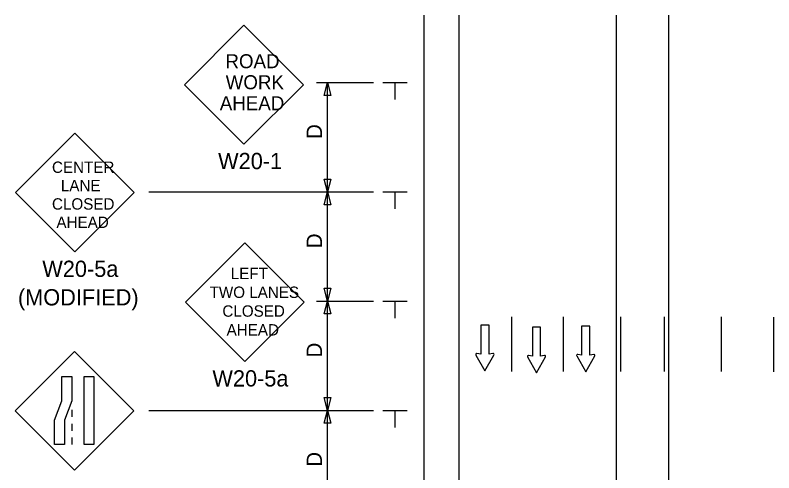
# Model space of a CAD drawing. Extents: x 16646 to 19498, y 2812 to 4437.
# Drawn here: x 16735.5 to 17082.8, y 3789.1 to 3998.5 of the extents above; entities that cross this region are included whole.
import ezdxf

# ---------------------------------------------------------------- set-up
doc = ezdxf.new("R2010")
doc.units = 0
for name, color, linetype in [('ALI_LEGAL_EX', 7, 'Continuous'), ('MT_SCRATCH_LEVEL_E', 7, 'Continuous'), ('PAVT_EDGE_EX', 7, 'Continuous'), ('TRAFFIC_SIGNS_PR', 7, 'Continuous'), ('TYPICAL_EX', 7, 'Continuous'), ('TYPICAL_TEXT_DIMEN_PR', 7, 'Continuous')]:
    doc.layers.add(name, color=color, linetype=linetype)

msp = doc.modelspace()

# ---------------------------------------------------------------- linework, layer by layer
at = {"layer": 'ALI_LEGAL_EX'}
for points in [[(16962.79, 3835.46), (16962.79, 3860.46)], [(16986.57, 3835.47), (16986.57, 3860.47)], [(17012.79, 3835.46), (17012.79, 3860.46)], [(17032.79, 3835.46), (17032.79, 3860.46)], [(17058.79, 3835.46), (17058.79, 3860.46)], [(17082.79, 3835.26), (17082.79, 3860.26)]]:
    msp.add_lwpolyline(points, dxfattribs=at)
at = {"layer": 'MT_SCRATCH_LEVEL_E'}
for p, q in [((16952.39, 3856.57), (16948.64, 3856.57)), ((16948.64, 3856.57), (16948.64, 3843.31)), ((16952.39, 3856.57), (16948.64, 3856.57)), ((16948.64, 3856.57), (16948.64, 3843.31)), ((16952.39, 3843.31), (16952.39, 3856.57)), ((16952.39, 3843.31), (16952.39, 3856.57)), ((16976.02, 3855.74), (16972.28, 3855.74)), ((16972.28, 3855.74), (16972.28, 3842.48)), ((16976.02, 3855.74), (16972.28, 3855.74)), ((16972.28, 3855.74), (16972.28, 3842.48)), ((16976.02, 3842.48), (16976.02, 3855.74)), ((16976.02, 3842.48), (16976.02, 3855.74)), ((16998.55, 3856.16), (16994.81, 3856.16)), ((16994.81, 3856.16), (16994.81, 3842.9)), ((16998.55, 3856.16), (16994.81, 3856.16)), ((16994.81, 3856.16), (16994.81, 3842.9)), ((16998.55, 3842.9), (16998.55, 3856.16)), ((16998.55, 3842.9), (16998.55, 3856.16)), ((16946.39, 3842.94), (16950.53, 3835.7)), ((16946.39, 3842.94), (16950.53, 3835.7)), ((16948.64, 3843.31), (16946.87, 3843.63)), ((16948.64, 3843.31), (16946.87, 3843.63)), ((16950.53, 3835.7), (16954.65, 3842.94)), ((16950.53, 3835.7), (16954.65, 3842.94)), ((16954.16, 3843.63), (16952.39, 3843.31)), ((16954.16, 3843.63), (16952.39, 3843.31)), ((16970.02, 3842.12), (16974.17, 3834.88)), ((16970.02, 3842.12), (16974.17, 3834.88)), ((16972.28, 3842.48), (16970.5, 3842.8)), ((16972.28, 3842.48), (16970.5, 3842.8)), ((16974.17, 3834.88), (16978.28, 3842.12)), ((16974.17, 3834.88), (16978.28, 3842.12)), ((16977.8, 3842.8), (16976.02, 3842.48)), ((16977.8, 3842.8), (16976.02, 3842.48)), ((16992.55, 3842.53), (16996.7, 3835.29)), ((16992.55, 3842.53), (16996.7, 3835.29)), ((16994.81, 3842.9), (16993.03, 3843.21)), ((16994.81, 3842.9), (16993.03, 3843.21)), ((16996.7, 3835.29), (17000.81, 3842.53)), ((16996.7, 3835.29), (17000.81, 3842.53)), ((17000.33, 3843.21), (16998.55, 3842.9)), ((17000.33, 3843.21), (16998.55, 3842.9))]:
    msp.add_line(p, q, dxfattribs=at)
for centre, start, end in [((16946.8, 3843.17), 80.0362, 209.7731), ((16946.8, 3843.17), 80.0362, 209.7731), ((16954.24, 3843.17), 330.4248, 99.9638), ((16954.24, 3843.17), 330.4248, 99.9638), ((16970.43, 3842.34), 80.0362, 209.7731), ((16970.43, 3842.34), 80.0362, 209.7731), ((16977.87, 3842.34), 330.4248, 99.9638), ((16977.87, 3842.34), 330.4248, 99.9638), ((16992.96, 3842.75), 80.0362, 209.7731), ((16992.96, 3842.75), 80.0362, 209.7731), ((17000.4, 3842.75), 330.4248, 99.9638), ((17000.4, 3842.75), 330.4248, 99.9638)]:
    msp.add_arc(centre, 0.463, start, end, dxfattribs=at)
at = {"layer": 'PAVT_EDGE_EX'}
for p, q in [((16938.57, 3998.47), (16938.57, 3231.86)), ((17010.57, 3998.47), (17010.57, 3554.03)), ((17034.57, 3998.47), (17034.57, 3594.25)), ((16922.57, 3836.4), (16922.57, 3233.74)), ((17010.57, 3836.4), (17010.57, 3563.39)), ((17034.57, 3836.4), (17034.57, 3553.74))]:
    msp.add_line(p, q, dxfattribs=at)
at = {"layer": 'TRAFFIC_SIGNS_PR'}
for p, q in [((16840.2, 3993.84), (16813.02, 3966.65)), ((16867.39, 3966.65), (16840.2, 3993.84)), ((16813.02, 3966.65), (16840.2, 3939.47)), ((16840.2, 3939.47), (16867.39, 3966.65)), ((16762.74, 3944.43), (16735.59, 3917.28)), ((16789.89, 3917.28), (16762.74, 3944.43)), ((16735.59, 3917.28), (16762.74, 3890.13)), ((16762.74, 3890.13), (16789.89, 3917.28)), ((16840.62, 3894.29), (16813.46, 3867.14)), ((16867.77, 3867.14), (16840.62, 3894.29)), ((16813.46, 3867.14), (16840.62, 3839.99)), ((16840.62, 3839.99), (16867.77, 3867.14)), ((16762.62, 3844.6), (16735.47, 3817.45)), ((16789.77, 3817.45), (16762.62, 3844.6)), ((16735.47, 3817.45), (16762.62, 3790.3)), ((16761.37, 3817.94), (16761.37, 3814.74)), ((16762.62, 3790.3), (16789.77, 3817.45)), ((16761.37, 3811.54), (16761.37, 3808.34)), ((16761.37, 3805.14), (16761.37, 3801.94))]:
    msp.add_line(p, q, dxfattribs=at)
for points in [[(16761.37, 3833.19), (16761.37, 3822), (16758.03, 3813.12), (16758.03, 3801.94), (16753.53, 3801.94), (16753.53, 3813.12), (16756.88, 3822), (16756.88, 3833.19)], [(16771.51, 3833.19), (16771.51, 3801.94), (16767.02, 3801.94), (16767.02, 3833.19)]]:
    msp.add_lwpolyline(points, close=True, dxfattribs=at)
at = {"layer": 'TYPICAL_EX'}
msp.add_line((16922.57, 3998.47), (16922.57, 3232.23), dxfattribs=at)
at = {"layer": 'TYPICAL_TEXT_DIMEN_PR'}
for p, q in [((16873.47, 3967.62), (16899.47, 3967.62)), ((16876.9, 3961.75), (16878.47, 3967.62)), ((16878.47, 3917.62), (16878.47, 3967.62)), ((16878.47, 3967.62), (16880.04, 3961.75)), ((16903.72, 3967.62), (16914.97, 3967.62)), ((16909.35, 3967.62), (16909.35, 3959.83)), ((16878.47, 3961.75), (16876.9, 3961.75)), ((16880.04, 3961.75), (16878.47, 3961.75)), ((16878.47, 3917.62), (16876.9, 3923.48)), ((16876.9, 3923.48), (16878.47, 3923.48)), ((16878.47, 3923.48), (16880.04, 3923.48)), ((16880.04, 3923.48), (16878.47, 3917.62)), ((16796.6, 3917.62), (16899.47, 3917.62)), ((16873.47, 3917.62), (16899.47, 3917.62)), ((16876.9, 3911.75), (16878.47, 3917.62)), ((16878.47, 3867.62), (16878.47, 3917.62)), ((16878.47, 3917.62), (16880.04, 3911.75)), ((16903.72, 3917.62), (16914.97, 3917.62)), ((16909.35, 3917.62), (16909.35, 3909.83)), ((16878.47, 3911.75), (16876.9, 3911.75)), ((16880.04, 3911.75), (16878.47, 3911.75)), ((16878.47, 3867.62), (16876.9, 3873.48)), ((16876.9, 3873.48), (16878.47, 3873.48)), ((16878.47, 3873.48), (16880.04, 3873.48)), ((16880.04, 3873.48), (16878.47, 3867.62)), ((16873.47, 3867.62), (16899.47, 3867.62)), ((16873.47, 3867.62), (16899.47, 3867.62)), ((16876.9, 3861.75), (16878.47, 3867.62)), ((16878.47, 3817.62), (16878.47, 3867.62)), ((16878.47, 3867.62), (16880.04, 3861.75)), ((16903.72, 3867.62), (16914.97, 3867.62)), ((16909.35, 3867.62), (16909.35, 3859.83)), ((16878.47, 3861.75), (16876.9, 3861.75)), ((16880.04, 3861.75), (16878.47, 3861.75)), ((16878.47, 3817.62), (16876.9, 3823.48)), ((16876.9, 3823.48), (16878.47, 3823.48)), ((16878.47, 3823.48), (16880.04, 3823.48)), ((16880.04, 3823.48), (16878.47, 3817.62)), ((16796.6, 3817.62), (16899.47, 3817.62)), ((16873.47, 3817.62), (16899.47, 3817.62)), ((16876.9, 3811.75), (16878.47, 3817.62)), ((16878.47, 3767.62), (16878.47, 3817.62)), ((16878.47, 3817.62), (16880.04, 3811.75)), ((16903.72, 3817.62), (16914.97, 3817.62)), ((16909.35, 3817.62), (16909.35, 3809.83)), ((16878.47, 3811.75), (16876.9, 3811.75)), ((16880.04, 3811.75), (16878.47, 3811.75))]:
    msp.add_line(p, q, dxfattribs=at)

# ---------------------------------------------------------------- texts
at = {"layer": 'TRAFFIC_SIGNS_PR'}
for s, height, p in [('ROAD', 6.408, (16831.73, 3974.2)), ('WORK', 6.408, (16831.84, 3964.59)), ('AHEAD', 6.408, (16829.15, 3954.97)), ('W20-1', 7.449, (16828.36, 3928.01)), ('CENTER', 5.2, (16752.32, 3926.29)), ('LANE', 5.2, (16756.39, 3917.89)), ('CLOSED', 5.2, (16752.32, 3909.49)), ('AHEAD', 5.2, (16754.35, 3901.09)), ('W20-5a', 7.44, (16747.88, 3878.69)), ('LEFT', 5.2, (16834.15, 3877.68)), ('(MODIFIED)', 7.44, (16736.73, 3865.65)), ('TWO LANES', 5.2, (16824.48, 3869.08)), ('CLOSED', 5.2, (16830.33, 3860.48)), ('AHEAD', 5.2, (16832.27, 3851.88)), ('W20-5a', 7.44, (16825.76, 3828.55))]:
    msp.add_text(s, height=height, dxfattribs=at).set_placement(p)
at = {"layer": 'TYPICAL_TEXT_DIMEN_PR'}
for p in [(16875.91, 3941.83), (16875.91, 3891.83), (16875.91, 3841.83), (16875.91, 3791.83)]:
    msp.add_text('D', height=7, rotation=90, dxfattribs=at).set_placement(p)

doc.saveas('drawing.dxf')
